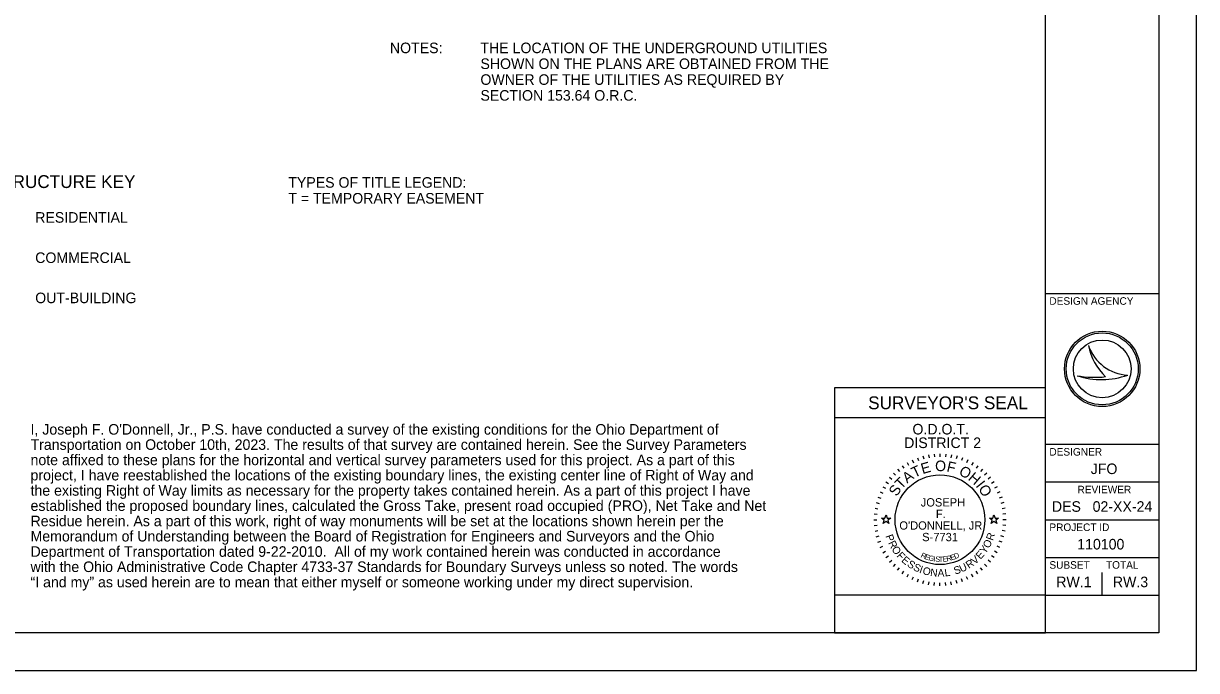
# Model space of a CAD drawing. Extents: x 63.4 to 97.4, y 0.4 to 22.4.
# Drawn here: x 81.86 to 97.41, y 0.42 to 9 of the extents above; entities that cross this region are included whole.
import ezdxf

# ---------------------------------------------------------------- set-up
doc = ezdxf.new("R2010")
doc.units = 0
for name, color, linetype in [('Default', 7, 'Continuous'), ('SH_Border', 7, 'Continuous'), ('SH_Cut_Line', 7, 'Continuous'), ('SH_Data', 7, 'Continuous'), ('SH_Text', 7, 'Continuous')]:
    doc.layers.add(name, color=color, linetype=linetype)

msp = doc.modelspace()

# ---------------------------------------------------------------- linework, layer by layer
at = {"layer": 'Default'}
for points in [[(93.236, 2.44), (93.283, 2.44), (93.297, 2.484), (93.312, 2.44), (93.359, 2.44), (93.321, 2.412), (93.335, 2.368), (93.297, 2.395), (93.259, 2.368), (93.274, 2.412)], [(94.666, 2.44), (94.713, 2.44), (94.727, 2.484), (94.742, 2.44), (94.789, 2.44), (94.751, 2.412), (94.765, 2.368), (94.727, 2.395), (94.689, 2.368), (94.704, 2.412)]]:
    msp.add_lwpolyline(points, close=True, dxfattribs=at)
at = {"layer": 'SH_Border'}
for p, q in [((95.412, 0.92), (95.412, 21.92)), ((95.412, 5.42), (96.912, 5.42)), ((95.412, 3.42), (96.912, 3.42)), ((95.412, 2.92), (96.912, 2.92)), ((95.412, 2.42), (96.912, 2.42)), ((95.412, 1.92), (96.912, 1.92)), ((95.412, 1.42), (96.912, 1.42))]:
    msp.add_line(p, q, dxfattribs=at)
msp.add_lwpolyline([(64.912, 21.92), (96.912, 21.92), (96.912, 0.92), (64.912, 0.92)], close=True, dxfattribs=at)
at = {"layer": 'SH_Cut_Line'}
msp.add_lwpolyline([(63.412, 0.42), (97.412, 0.42), (97.412, 22.42), (63.412, 22.42)], close=True, dxfattribs=at)
at = {"layer": 'SH_Data'}
for p, q in [((95.98, 4.729), (95.98, 4.729)), ((96.162, 4.42), (96.162, 4.42)), ((95.829, 4.329), (95.829, 4.329)), ((96.5, 4.338), (96.5, 4.338)), ((95.412, 4.17), (92.612, 4.17)), ((92.612, 4.17), (92.612, 0.92)), ((95.412, 0.92), (95.412, 4.17)), ((95.412, 3.77), (92.612, 3.77)), ((93.86, 3.281), (93.867, 3.242)), ((93.936, 3.291), (93.94, 3.252)), ((94.012, 3.295), (94.012, 3.255)), ((94.089, 3.291), (94.085, 3.252)), ((94.164, 3.281), (94.157, 3.242)), ((93.51, 3.136), (93.533, 3.104)), ((93.575, 3.177), (93.595, 3.143)), ((93.643, 3.213), (93.659, 3.176)), ((93.713, 3.242), (93.727, 3.204)), ((93.786, 3.265), (93.796, 3.226)), ((94.239, 3.265), (94.228, 3.226)), ((94.312, 3.242), (94.298, 3.204)), ((94.382, 3.213), (94.365, 3.176)), ((94.45, 3.177), (94.43, 3.143)), ((94.514, 3.136), (94.491, 3.104)), ((93.342, 2.982), (93.373, 2.956)), ((93.394, 3.038), (93.422, 3.01)), ((93.45, 3.09), (93.476, 3.059)), ((94.575, 3.09), (94.549, 3.059)), ((94.631, 3.038), (94.603, 3.01)), ((94.683, 2.982), (94.652, 2.956)), ((93.255, 2.857), (93.289, 2.837)), ((93.296, 2.922), (93.328, 2.899)), ((94.729, 2.922), (94.696, 2.899)), ((94.77, 2.857), (94.735, 2.837)), ((93.167, 2.646), (93.206, 2.636)), ((93.19, 2.719), (93.228, 2.705)), ((93.219, 2.79), (93.256, 2.773)), ((94.805, 2.79), (94.769, 2.773)), ((94.835, 2.719), (94.797, 2.705)), ((94.857, 2.646), (94.819, 2.636)), ((93.141, 2.496), (93.18, 2.492)), ((93.151, 2.572), (93.19, 2.565)), ((94.874, 2.572), (94.835, 2.565)), ((94.884, 2.496), (94.844, 2.492)), ((93.137, 2.42), (93.177, 2.42)), ((93.141, 2.343), (93.18, 2.347)), ((94.884, 2.343), (94.844, 2.347)), ((94.887, 2.42), (94.847, 2.42)), ((93.151, 2.268), (93.19, 2.275)), ((93.167, 2.193), (93.206, 2.204)), ((94.857, 2.193), (94.819, 2.204)), ((94.874, 2.268), (94.835, 2.275)), ((93.19, 2.12), (93.228, 2.134)), ((93.219, 2.05), (93.256, 2.067)), ((94.805, 2.05), (94.769, 2.067)), ((94.835, 2.12), (94.797, 2.134)), ((93.255, 1.982), (93.289, 2.002)), ((93.296, 1.918), (93.328, 1.941)), ((93.342, 1.857), (93.373, 1.883)), ((94.683, 1.857), (94.652, 1.883)), ((94.729, 1.918), (94.696, 1.941)), ((94.77, 1.982), (94.735, 2.002)), ((93.394, 1.801), (93.422, 1.829)), ((93.45, 1.749), (93.476, 1.78)), ((93.51, 1.703), (93.533, 1.736)), ((94.514, 1.703), (94.491, 1.736)), ((94.575, 1.749), (94.549, 1.78)), ((94.631, 1.801), (94.603, 1.829)), ((96.162, 1.42), (96.162, 1.72)), ((93.575, 1.662), (93.595, 1.697)), ((93.643, 1.627), (93.659, 1.663)), ((93.713, 1.597), (93.727, 1.635)), ((93.786, 1.575), (93.796, 1.613)), ((93.86, 1.558), (93.867, 1.597)), ((93.936, 1.548), (93.94, 1.588)), ((94.012, 1.545), (94.012, 1.585)), ((94.089, 1.548), (94.085, 1.588)), ((94.164, 1.558), (94.157, 1.597)), ((94.239, 1.575), (94.228, 1.613)), ((94.312, 1.597), (94.298, 1.635)), ((94.382, 1.627), (94.365, 1.663)), ((94.45, 1.662), (94.43, 1.697)), ((95.412, 0.92), (92.612, 0.92))]:
    msp.add_line(p, q, dxfattribs=at)
msp.add_lwpolyline([(95.412, 0.92), (95.412, 1.42), (92.612, 1.42), (92.612, 0.92)], close=True, dxfattribs=at)
for centre, radius in [((96.162, 4.42), 0.5), ((96.162, 4.42), 0.477), ((96.162, 4.42), 0.477), ((96.162, 4.42), 0.382), ((94.012, 2.42), 0.595)]:
    msp.add_circle(centre, radius, dxfattribs=at)
for centre, radius, start, end in [((96.528, 4.917), 0.58, 198.9257, 198.9319), ((96.759, 4.89), 0.796, 191.6379, 191.6421), ((96.528, 4.917), 0.58, 198.9319, 267.1657), ((96.759, 4.89), 0.796, 191.6421, 226.0947), ((96.06, 5.574), 1.266, 259.4964, 259.4995), ((96.152, 5.29), 1.013, 251.4527, 251.4576), ((96.152, 5.29), 1.013, 251.4576, 290.0832), ((96.06, 5.574), 1.266, 259.4995, 276.6672)]:
    msp.add_arc(centre, radius, start, end, dxfattribs=at)

# ---------------------------------------------------------------- texts
for s, height, p in [('DESIGN AGENCY', 0.1, (95.462, 5.27)), ("SURVEYOR'S SEAL", 0.17, (93.06, 3.885)), ('O.D.O.T.', 0.14, (93.647, 3.55)), ('DISTRICT 2', 0.14, (93.537, 3.37)), ('DESIGNER', 0.1, (95.462, 3.27)), ('JFO', 0.14, (96.01, 3.025)), ('REVIEWER', 0.1, (95.834, 2.77)), ('JOSEPH', 0.11, (93.757, 2.595)), ('DES', 0.14, (95.495, 2.525)), ('02-XX-24', 0.14, (96.035, 2.525)), ('F.', 0.11, (93.958, 2.441)), ("O'DONNELL, JR.", 0.11, (93.474, 2.288)), ('PROJECT ID', 0.1, (95.462, 2.27)), ('S-7731', 0.11, (93.776, 2.135)), ('110100', 0.14, (95.831, 2.025)), ('SUBSET', 0.1, (95.462, 1.77)), ('TOTAL', 0.1, (96.212, 1.77)), ('RW.1', 0.14, (95.553, 1.525)), ('RW.3', 0.14, (96.303, 1.525))]:
    msp.add_text(s, height=height, dxfattribs=at).set_placement(p)
for s, height, rotation, p in [('T', 0.14, 25.7167, (93.674, 2.972)), ('E', 0.14, 15.7571, (93.781, 3.024)), ('O', 0.14, 359.7812, (93.947, 3.064)), ('F', 0.14, 347.4362, (94.093, 3.061)), ('O', 0.14, 332.2586, (94.252, 3.021)), ('T', 0.14, 46.4344, (93.501, 2.816)), ('A', 0.14, 36.4747, (93.576, 2.898)), ('H', 0.14, 319.9136, (94.375, 2.956)), ('S', 0.14, 57.1924, (93.44, 2.721)), ('I', 0.14, 308.367, (94.479, 2.868)), ('O', 0.14, 303.1491, (94.514, 2.829)), ('P', 0.1, 289.7431, (93.288, 2.204)), ('R', 0.1, 70.983, (94.713, 2.136)), ('R', 0.1, 296.9802, (93.322, 2.112)), ('O', 0.1, 304.7158, (93.365, 2.028)), ('Y', 0.1, 55.5058, (94.612, 1.96)), ('O', 0.1, 62.7428, (94.662, 2.033)), ('F', 0.1, 312.956, (93.432, 1.936)), ('E', 0.1, 319.6885, (93.493, 1.87)), ('S', 0.1, 326.9255, (93.568, 1.808)), ('R', 0.07, 334.487, (93.75, 1.925)), ('E', 0.07, 341.04, (93.803, 1.9)), ('G', 0.07, 347.4752, (93.854, 1.882)), ('I', 0.07, 353.7858, (93.921, 1.867)), ('S', 0.07, 356.8926, (93.948, 1.863)), ('T', 0.07, 3.0061, (93.998, 1.858)), ('E', 0.07, 6.0117, (94.051, 1.861)), ('R', 0.07, 11.9184, (94.105, 1.867)), ('E', 0.07, 17.6836, (94.162, 1.88)), ('D', 0.07, 23.3052, (94.213, 1.897)), ('R', 0.1, 33.296, (94.394, 1.767)), ('V', 0.1, 41.0316, (94.474, 1.82)), ('E', 0.1, 48.2687, (94.549, 1.887)), ('S', 0.1, 334.1626, (93.648, 1.757)), ('I', 0.1, 341.3997, (93.731, 1.718)), ('O', 0.1, 345.1351, (93.774, 1.702)), ('N', 0.1, 353.3752, (93.878, 1.675)), ('A', 0.1, 1.1108, (93.981, 1.664)), ('L', 0.1, 8.3479, (94.079, 1.666)), ('S', 0.1, 18.3234, (94.213, 1.691)), ('U', 0.1, 25.5604, (94.296, 1.718))]:
    msp.add_text(s, height=height, rotation=rotation, dxfattribs=at).set_placement(p)
at = {"layer": 'SH_Text'}
for s, height, p in [('NOTES:', 0.14, (86.721, 8.606)), ('THE LOCATION OF THE UNDERGROUND UTILITIES', 0.14, (87.921, 8.606)), ('SHOWN ON THE PLANS ARE OBTAINED FROM THE', 0.14, (87.921, 8.396)), ('OWNER OF THE UTILITIES AS REQUIRED BY', 0.14, (87.921, 8.186)), ('SECTION 153.64 O.R.C.', 0.14, (87.921, 7.976)), ('STRUCTURE KEY', 0.17, (81.429, 6.818)), ('TYPES OF TITLE LEGEND:', 0.14, (85.374, 6.822)), ('T = TEMPORARY EASEMENT', 0.14, (85.374, 6.612)), ('RESIDENTIAL', 0.14, (82.02, 6.358)), ('COMMERCIAL', 0.14, (82.02, 5.824)), ('OUT-BUILDING', 0.14, (82.02, 5.291)), ("I, Joseph F. O'Donnell, Jr., P.S. have conducted a survey of the existing conditions for the Ohio Department of ", 0.14, (81.958, 3.548)), ('Transportation on October 10th, 2023. The results of that survey are contained herein. See the Survey Parameters', 0.14, (81.958, 3.346)), ('note affixed to these plans for the horizontal and vertical survey parameters used for this project. As a part of this', 0.14, (81.958, 3.143)), ('project, I have reestablished the locations of the existing boundary lines, the existing center line of Right of Way and', 0.14, (81.958, 2.941)), ('the existing Right of Way limits as necessary for the property takes contained herein. As a part of this project I have', 0.14, (81.958, 2.738)), ('established the proposed boundary lines, calculated the Gross Take, present road occupied (PRO), Net Take and Net', 0.14, (81.958, 2.536)), ('Residue herein. As a part of this work, right of way monuments will be set at the locations shown herein per the ', 0.14, (81.958, 2.333)), ('Memorandum of Understanding between the Board of Registration for Engineers and Surveyors and the Ohio ', 0.14, (81.958, 2.131)), ('Department of Transportation dated 9-22-2010.  All of my work contained herein was conducted in accordance ', 0.14, (81.958, 1.928)), ('with the Ohio Administrative Code Chapter 4733-37 Standards for Boundary Surveys unless so noted. The words ', 0.14, (81.958, 1.726)), ('“I and my” as used herein are to mean that either myself or someone working under my direct supervision.', 0.14, (81.958, 1.523))]:
    msp.add_text(s, height=height, dxfattribs=at).set_placement(p)

doc.saveas('drawing.dxf')
